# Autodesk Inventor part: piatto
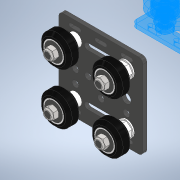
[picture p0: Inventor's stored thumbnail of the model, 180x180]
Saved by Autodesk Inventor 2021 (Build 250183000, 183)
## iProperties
Created: 2026-01
Part Number: piatto
Material: Generico
Document SubType Name: Modeling
Designer: hp
Density: 1 g/cm^3
Appearance: Default
Author: hp
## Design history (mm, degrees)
feature "Solido1"
feature "Solido2"
feature "Solido3"
feature "Solido4"
feature "Solido5"
feature "Solido6"
feature "Solido7"
feature "Solido8"
feature "Solido9"
feature "Solido10"
feature "Solido11"
feature "Solido12"
feature "Solido13"
feature "Solido14"
feature "Solido15"
feature "Solido16"
feature "Solido17"
feature "Solido18"
feature "Solido19"
feature "Solido20"
feature "Solido21"
feature "Solido22"
feature "Solido23"
feature "Solido24"
feature "Solido25"
feature "Solido26"
feature "Solido27"
feature "Solido28"
feature "Solido29"
body "Solid1"
body "Solid2"
body "Solid3"
body "Solid4"
body "Solid5"
body "Solid6"
body "Solid7"
body "Solid8"
body "Solid9"
body "Solid10"
body "Solid11"
body "Solid12"
body "Solid13"
body "Solid14"
body "Solid15"
body "Solid16"
body "Solid17"
body "Solid18"
body "Solid19"
body "Solid20"
body "Solid21"
body "Solid22"
body "Solid23"
body "Solid24"
body "Solid25"
body "Solid26"
body "Solid27"
body "Solid28"
body "Solid29"
